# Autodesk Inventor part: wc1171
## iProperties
Shininess: 64.0
Length Units: 11272
Angle Units: 11279
Time Units: 11290
Mass Units: 11286
Length Display Precision: 3
Angle Display Precision: 2
Compacted: True
Part Number: wc1171
Document SubType Name: Modeling
Created: 2004-08
Designer: John Blackburn
Manufacturer: Standard
Standards Organization: Custom
Material: Phenolic
Density: 0.0
Volumn: 0.0
Area: 0.0
PropertySet Name: Model Information
Control State: 0
Master: False
Checked Out: False
Author: John Blackburn
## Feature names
1. Base1
